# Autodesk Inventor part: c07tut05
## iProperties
Shininess: 64.0
Length Units: 11269
Angle Units: 11279
Time Units: 11290
Mass Units: 11283
Length Display Precision: 3
Angle Display Precision: 2
Compacted: True
Part Number: c07tut05
Document SubType Name: Modeling
Created: 2002-12
Designer: deepak
Density: 0.0
Volumn: 0.0
Area: 0.0
PropertySet Name: Model Information
Control State: 0
Master: False
Checked Out: False
Author: deepak
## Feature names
1. Loft2
